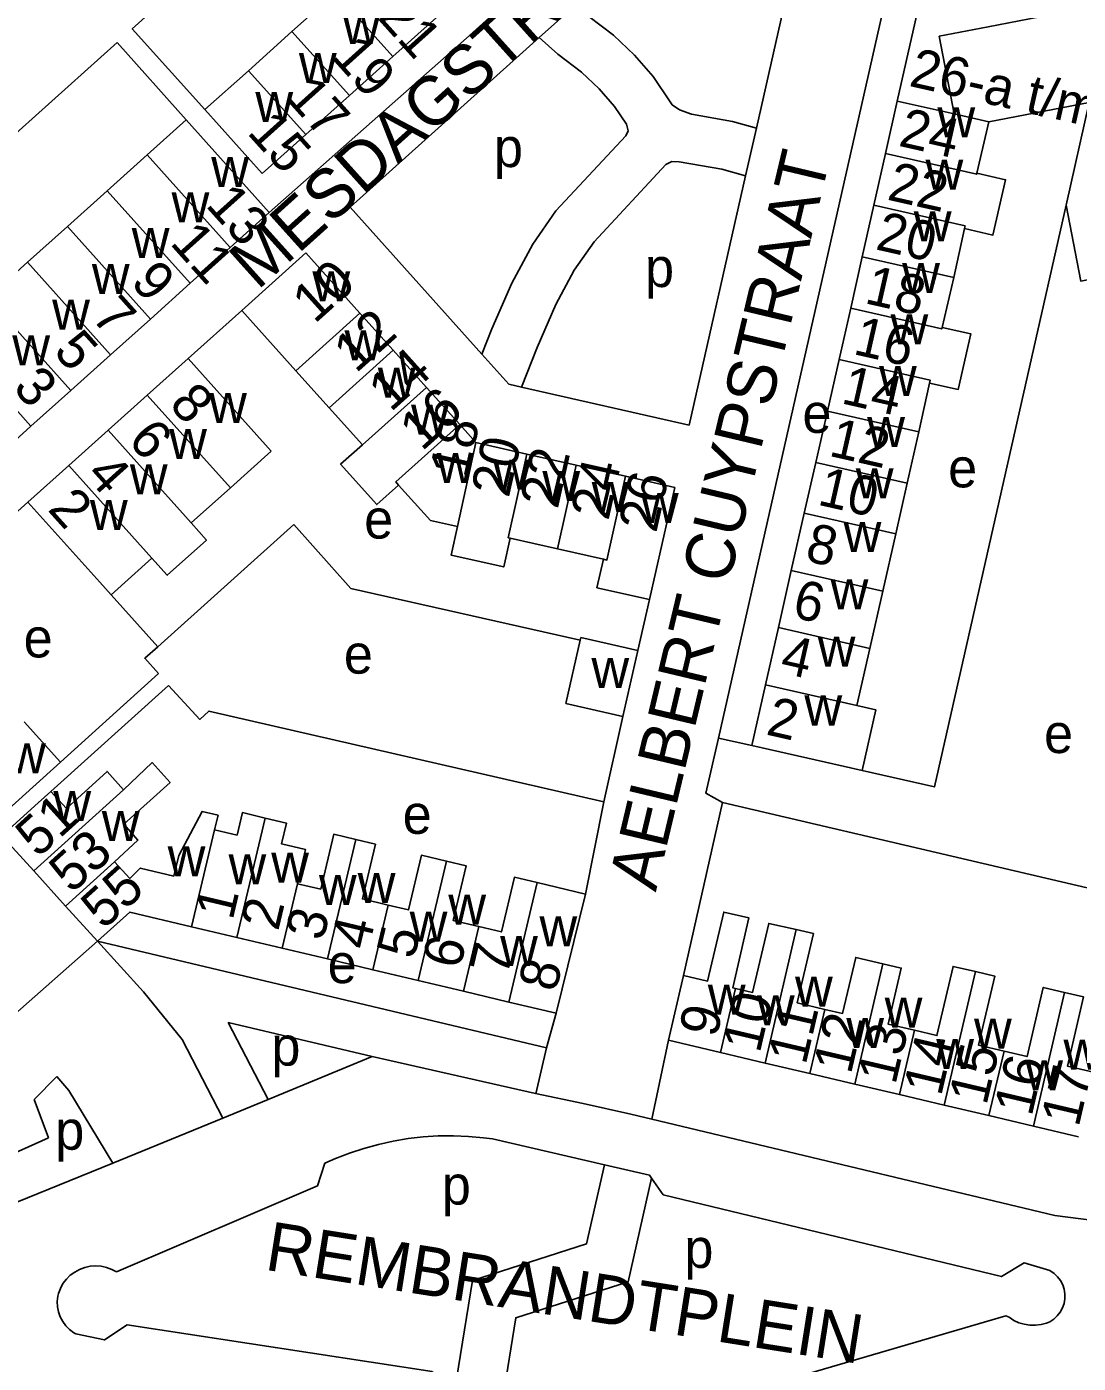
# Model space of a CAD drawing. Extents: x 161775 to 163181, y 382878 to 383925.
# Drawn here: x 162936.2 to 163043.8, y 383281.3 to 383418.1 of the extents above; entities that cross this region are included whole.
import ezdxf

# ---------------------------------------------------------------- set-up
doc = ezdxf.new("R2010")
doc.units = 0
for name, color, linetype in [('BLT_Basislijn', 7, 'Continuous'), ('BLT_Bebouwing', 7, 'Continuous'), ('BLT_Centroide', 7, 'Continuous'), ('BLT_Huisnummer', 7, 'Continuous'), ('BLT_Huisnummer_ tussenligend', 7, 'Continuous'), ('BLT_Huisnummer_reeks', 7, 'Continuous'), ('BLT_Onderverdeling_panden', 7, 'Continuous'), ('BLT_Straatnaam', 7, 'Continuous'), ('BLT_Vlakafsluiter', 7, 'Continuous')]:
    doc.layers.add(name, color=color, linetype=linetype)

msp = doc.modelspace()

# ---------------------------------------------------------------- linework, layer by layer
at = {"layer": 'BLT_Basislijn'}
for p, q in [((162952.51, 383408.57), (162945.42, 383416.49)), ((163034.67, 383408.37), (163044.96, 383410.33)), ((163042.59, 383399.83), (163044.96, 383410.33)), ((162952.69, 383384.12), (162958.19, 383389.05)), ((162949.59, 383354.63), (162963.53, 383367.13)), ((162944.81, 383359.95), (162949.59, 383354.63)), ((162939.61, 383342.8), (162949.66, 383351.88)), ((162950.67, 383350.64), (162938.65, 383339.82)), ((163010.41, 383344.51), (163006.99, 383345.28)), ((162995.25, 383338.75), (162993.38, 383329.29)), ((163007.4, 383338.67), (163003.41, 383320.96)), ((162934.36, 383316.49), (162943.4, 383324.47)), ((162943.4, 383324.47), (162948.14, 383319.29)), ((162943.4, 383324.47), (162989.4, 383313.55)), ((162948.14, 383319.29), (162952.07, 383314.42)), ((162990.37, 383317.12), (162989.4, 383313.55)), ((162960.89, 383308.28), (162956.8, 383316.15)), ((162956.8, 383316.15), (162971.54, 383312.66)), ((162952.07, 383314.42), (162956.25, 383306.37)), ((163001.88, 383314.33), (163000.17, 383306.27)), ((162960.89, 383308.28), (162971.54, 383312.66)), ((162971.54, 383312.66), (162988.26, 383308.87)), ((162989.4, 383313.55), (162988.29, 383308.86)), ((162936.92, 383308.26), (162939.26, 383310.63)), ((162940.47, 383309.19), (162939.26, 383310.63)), ((162940.47, 383309.19), (162944.98, 383301.74)), ((162936.92, 383308.26), (162938.4, 383304.35)), ((162956.25, 383306.37), (162960.89, 383308.28)), ((162944.98, 383301.74), (162956.25, 383306.37)), ((163000.17, 383306.27), (163041.43, 383296.38)), ((162933.27, 383302.06), (162938.4, 383304.35)), ((162983.87, 383304.23), (162995.33, 383301.58)), ((162935.16, 383297.75), (162944.98, 383301.74))]:
    msp.add_line(p, q, dxfattribs=at)
for points in [[(162983.5, 383450.63), (162946.98, 383417.89), (162954.42, 383409.61)], [(162961.01, 383399.09), (163011.63, 383443.87)], [(163014.03, 383439.76), (163016.83, 383434.05), (163010.88, 383407.73)], [(163027.33, 383426.47), (163025.28, 383426.07), (163006.99, 383345.28)], [(162992.39, 383420.35), (162988.64, 383416.99)], [(162992.39, 383420.35), (162993.74, 383419.16), (162996.25, 383417.23), (162998.41, 383415.18), (163000.3, 383412.99), (163002.07, 383410.41), (163002.26, 383410.11), (163003, 383409.58)], [(162988.64, 383416.99), (162969.28, 383399.62), (162982.78, 383384.57)], [(162988.64, 383416.99), (162990.56, 383415.3), (162992.99, 383413.43), (162994.78, 383411.73), (162996.34, 383409.93), (162997.57, 383408.14), (162997.75, 383407.45)], [(162945.42, 383416.49), (162916.97, 383390.95)], [(163010.88, 383407.73), (163008.44, 383408.41), (163004.25, 383409.14), (163003, 383409.58)], [(162982.78, 383384.57), (162983.81, 383387.18), (162985.83, 383391.86), (162987.98, 383395.83), (162990.36, 383399.24), (162997.52, 383406.94), (162997.75, 383407.45)], [(163010.88, 383407.73), (163009.77, 383402.85)], [(162986.83, 383381.2), (162988.43, 383385.27), (162990.33, 383389.67), (162992.24, 383393.19), (162994.26, 383396.09), (163001.61, 383404), (163002.23, 383404.29)], [(163009.77, 383402.85), (163007.34, 383403.53), (163002.96, 383404.28), (163002.23, 383404.29)], [(163009.77, 383402.85), (163003.99, 383377.31)], [(163042.59, 383399.83), (163029.12, 383340.28), (163021.72, 383341.97)], [(163042.59, 383399.83), (163044.1, 383392.05), (163051.6, 383393.51)], [(162982.78, 383384.57), (162985.54, 383381.49), (162986.83, 383381.2)], [(162986.83, 383381.2), (163003.99, 383377.31)], [(162936.29, 383369.41), (162924.89, 383359.2)], [(162963.53, 383367.13), (162969.36, 383360.6), (162992.84, 383355.29)], [(162999.95, 383359.45), (162998.76, 383354.25)], [(162949.66, 383351.88), (162948.25, 383353.45), (162949.59, 383354.63)], [(162950.67, 383350.64), (162953.9, 383347.18), (162954.82, 383348.03), (162995.25, 383338.75)], [(162997.22, 383347.48), (162995.25, 383338.75)], [(163006.99, 383345.28), (163005.71, 383339.63), (163007.4, 383338.67)], [(163057.6, 383326.93), (163007.4, 383338.67)], [(162967.79, 383302.22), (162969.23, 383302.78), (162970.7, 383303.27), (162972.19, 383303.68), (162973.7, 383304.02), (162975.23, 383304.27), (162976.77, 383304.45), (162978.31, 383304.54), (162979.86, 383304.56), (162981.41, 383304.5), (162982.95, 383304.35), (162983.87, 383304.23)], [(162945.37, 383290.62), (162965.93, 383299.43), (162966.7, 383301.75), (162967.79, 383302.22)], [(162995.33, 383301.58), (162993.5, 383293.49), (162981.8, 383289.74), (162979.98, 383278.38)], [(162995.33, 383301.58), (162999.95, 383300.52), (163000.15, 383300.23)], [(163000.15, 383300.23), (162997.74, 383289.6), (162986.25, 383285.92), (162984.93, 383277.67)], [(163000.15, 383300.23), (163001.34, 383298.51), (163035.98, 383290.15), (163038.3, 383291.54), (163040.92, 383290.77)], [(163041.43, 383296.38), (163085.37, 383290.76), (163092.07, 383290.04)], [(162945.37, 383290.62), (162944.87, 383290.88), (162944.34, 383291.08), (162943.79, 383291.2), (162943.22, 383291.24), (162942.66, 383291.2), (162942.11, 383291.08), (162941.58, 383290.88), (162941.08, 383290.61), (162940.63, 383290.27), (162940.23, 383289.88), (162939.88, 383289.43), (162939.61, 383288.93), (162939.41, 383288.41), (162939.34, 383288.14)], [(163040.92, 383285.51), (163041.33, 383285.78), (163041.69, 383286.11), (163041.99, 383286.5), (163042.23, 383286.93), (163042.39, 383287.39), (163042.47, 383287.87), (163042.48, 383288.36), (163042.4, 383288.84), (163042.25, 383289.3), (163042.02, 383289.74), (163041.73, 383290.13), (163041.38, 383290.47), (163040.92, 383290.77)], [(162939.34, 383288.14), (162939.28, 383287.6), (162939.31, 383287.06), (162939.42, 383286.52), (162939.6, 383286.01), (162939.85, 383285.53), (162940.18, 383285.1), (162940.56, 383284.71), (162941, 383284.39), (162941.19, 383284.27)], [(162979.98, 383278.38), (162978.77, 383278.55), (162977.68, 383280.41), (162946.45, 383285.2), (162944.13, 383283.65), (162941.19, 383284.27)], [(163036.75, 383285.98), (163036.44, 383286.13), (163016.34, 383280.25), (163014.95, 383278.24), (163007.37, 383275.92)], [(163036.75, 383285.98), (163037.24, 383285.66), (163037.76, 383285.42), (163038.31, 383285.26), (163038.88, 383285.17), (163039.46, 383285.16), (163040.03, 383285.23), (163040.59, 383285.38), (163040.92, 383285.51)]]:
    msp.add_lwpolyline(points, dxfattribs=at)
at = {"layer": 'BLT_Bebouwing'}
for p, q in [((162973.67, 383415.05), (162978.12, 383419.05)), ((163039.92, 383419.12), (163034.62, 383418.1)), ((162969.21, 383411.05), (162973.67, 383415.05)), ((162964.75, 383407.05), (162969.21, 383411.05)), ((163024.12, 383405.11), (163025.3, 383410.49)), ((163031.13, 383409.17), (163025.3, 383410.49)), ((162960.29, 383403.06), (162954.42, 383409.61)), ((163034.67, 383408.37), (163031.13, 383409.17)), ((163034.67, 383408.37), (163033.47, 383403.12)), ((162960.29, 383403.06), (162964.75, 383407.05)), ((163022.92, 383399.82), (163024.12, 383405.11)), ((163021.73, 383394.55), (163022.92, 383399.82)), ((163032.19, 383397.44), (163031.09, 383392.43)), ((162958.19, 383389.05), (162964.74, 383394.95)), ((163020.54, 383389.29), (163021.73, 383394.55)), ((163031.09, 383392.43), (163029.9, 383387.31)), ((163019.35, 383384.02), (163020.54, 383389.29)), ((162963.73, 383382.88), (162958.19, 383389.05)), ((162948.51, 383380.39), (162952.69, 383384.12)), ((162952.69, 383384.12), (162961.19, 383374.64)), ((163018.15, 383378.75), (163019.35, 383384.02)), ((162967.14, 383379.09), (162963.73, 383382.88)), ((163028.62, 383381.61), (163027.52, 383376.63)), ((162944.49, 383376.79), (162948.51, 383380.39)), ((163016.96, 383373.48), (163018.15, 383378.75)), ((162940.47, 383373.18), (162944.49, 383376.79)), ((163027.52, 383376.63), (163026.33, 383371.36)), ((162957.02, 383370.9), (162961.19, 383374.64)), ((162936.29, 383369.41), (162940.47, 383373.18)), ((163015.79, 383368.29), (163016.96, 383373.48)), ((162953, 383367.3), (162957.02, 383370.9)), ((162999.95, 383359.45), (163002.52, 383370.94)), ((163026.33, 383371.36), (163025.15, 383366.17)), ((162936.29, 383369.41), (162943.64, 383361.25)), ((163014.46, 383362.43), (163015.79, 383368.29)), ((163025.15, 383366.17), (163023.83, 383360.31)), ((162944.81, 383359.95), (162948.98, 383363.69)), ((163013.14, 383356.58), (163014.46, 383362.43)), ((162943.64, 383361.25), (162944.81, 383359.95)), ((163023.83, 383360.31), (163022.5, 383354.46)), ((163011.81, 383350.73), (163013.14, 383356.58)), ((162992.84, 383355.29), (162991.37, 383348.8)), ((162992.9, 383355.57), (162992.84, 383355.29)), ((162992.9, 383355.57), (162998.76, 383354.25)), ((162998.76, 383354.25), (162997.22, 383347.48)), ((163022.5, 383354.46), (163021.18, 383348.61)), ((163010.41, 383344.51), (163011.81, 383350.73)), ((162997.22, 383347.48), (162991.37, 383348.8)), ((162939.61, 383342.8), (162935.91, 383346.92)), ((163019.77, 383342.39), (163010.41, 383344.51)), ((162936.89, 383331.68), (162946.09, 383339.99)), ((162936.89, 383331.68), (162933.63, 383335.28)), ((162940.15, 383328.08), (162945.17, 383332.61)), ((162940.15, 383328.08), (162936.89, 383331.68)), ((162988.42, 383330.47), (162993.38, 383329.29)), ((162993.38, 383329.29), (162990.37, 383317.12)), ((162943.4, 383324.47), (162940.15, 383328.08)), ((162957.69, 383324.86), (162953.05, 383325.96)), ((162962.33, 383323.76), (162957.69, 383324.86)), ((162966.97, 383322.66), (162962.33, 383323.76)), ((162971.6, 383321.55), (162966.97, 383322.66)), ((162976.24, 383320.45), (162971.6, 383321.55)), ((163001.88, 383314.33), (163003.41, 383320.96)), ((162980.88, 383319.35), (162976.24, 383320.45)), ((162985.52, 383318.25), (162980.88, 383319.35)), ((162990.37, 383317.12), (162985.52, 383318.25)), ((163007.2, 383313.08), (163001.88, 383314.33)), ((163011.78, 383312), (163007.2, 383313.08)), ((163016.36, 383310.93), (163011.78, 383312)), ((163020.95, 383309.85), (163016.36, 383310.93)), ((163025.53, 383308.77), (163020.95, 383309.85)), ((163030.11, 383307.69), (163025.53, 383308.77)), ((163034.69, 383306.62), (163030.11, 383307.69)), ((163039.27, 383305.54), (163034.69, 383306.62)), ((163043.86, 383304.46), (163039.27, 383305.54))]:
    msp.add_line(p, q, dxfattribs=at)
for points in [[(163025.3, 383410.49), (163028.06, 383422.69), (163027.33, 383426.47)], [(162963.33, 383417.6), (162967.79, 383421.6)], [(163034.62, 383418.1), (163029.61, 383417.13), (163031.13, 383409.17)], [(162958.87, 383413.6), (162963.33, 383417.6)], [(162954.42, 383409.61), (162958.87, 383413.6)], [(162952.51, 383408.57), (162948.49, 383404.97)], [(162961.01, 383399.09), (162952.51, 383408.57)], [(162948.49, 383404.97), (162944.41, 383401.31)], [(163033.47, 383403.12), (163036.4, 383402.44), (163035.11, 383396.77), (163032.19, 383397.44)], [(162944.41, 383401.31), (162940.33, 383397.65)], [(162956.99, 383395.49), (162961.01, 383399.09)], [(162940.33, 383397.65), (162936.25, 383393.99)], [(162952.92, 383391.83), (162956.99, 383395.49)], [(162964.74, 383394.95), (162970.28, 383388.77)], [(162936.25, 383393.99), (162932.17, 383390.33)], [(162948.84, 383388.17), (162952.92, 383391.83)], [(162944.76, 383384.51), (162948.84, 383388.17)], [(162970.28, 383388.77), (162973.69, 383384.97)], [(163029.9, 383387.31), (163032.83, 383386.66), (163031.55, 383380.96), (163028.62, 383381.61)], [(162940.68, 383380.85), (162944.76, 383384.51)], [(162973.69, 383384.97), (162977.09, 383381.17)], [(162977.09, 383381.17), (162980.5, 383377.38)], [(162936.6, 383377.2), (162940.68, 383380.85)], [(162970.54, 383375.3), (162967.14, 383379.09)], [(162932.55, 383373.56), (162936.6, 383377.2)], [(162980.5, 383377.38), (162982.16, 383375.52)], [(162982.16, 383375.52), (162987.39, 383374.34)], [(162974.25, 383371.17), (162972.01, 383369.17), (162968.31, 383373.3), (162970.54, 383375.3)], [(162987.39, 383374.34), (162992.44, 383373.2)], [(162992.44, 383373.2), (162997.49, 383372.07)], [(162997.49, 383372.07), (163002.52, 383370.94)], [(162980.27, 383366.94), (162977.51, 383367.55), (162974.25, 383371.17)], [(162948.98, 383363.69), (162950.55, 383361.94), (162954.57, 383365.55), (162953, 383367.3)], [(162980.27, 383366.94), (162979.62, 383364.01), (162985.01, 383362.8), (162985.67, 383365.74)], [(162985.67, 383365.74), (162990.52, 383364.64)], [(162990.52, 383364.64), (162995.22, 383363.58)], [(162995.22, 383363.58), (162994.56, 383360.66), (162999.95, 383359.45)], [(163021.18, 383348.61), (163023.11, 383348.18), (163021.72, 383341.97)], [(162932.49, 383336.4), (162939.61, 383342.8)], [(162945.17, 383332.61), (162947.56, 383334.83), (162946.1, 383336.45), (162950.84, 383340.74), (162949.02, 383342.76), (162946.09, 383339.99)], [(162938.65, 383339.82), (162940.23, 383338.08), (162944.4, 383341.86), (162946.09, 383339.99)], [(163021.72, 383341.97), (163019.77, 383342.39)], [(162933.63, 383335.28), (162937.34, 383338.64), (162938.65, 383339.82)], [(162955.41, 383335.89), (162955.76, 383337.37), (162954.13, 383337.76), (162951.74, 383333.26), (162951.24, 383331.15)], [(162960.59, 383337.08), (162958.26, 383337.64), (162957.71, 383335.34), (162955.41, 383335.89)], [(162963.89, 383330.36), (162964.72, 383333.86), (162962.26, 383334.44), (162962.76, 383336.57), (162960.59, 383337.08)], [(162969.87, 383334.88), (162967.6, 383335.42), (162966.27, 383329.81), (162963.89, 383330.36)], [(162973.17, 383328.17), (162970.55, 383328.8), (162971.88, 383334.4), (162969.87, 383334.88)], [(162979.14, 383332.68), (162976.59, 383333.28), (162975.25, 383327.68), (162973.17, 383328.17)], [(162951.24, 383331.15), (162947.8, 383331.96), (162946.71, 383330.91), (162945.17, 383332.61)], [(162982.45, 383325.97), (162979.85, 383326.59), (162981.18, 383332.19), (162979.14, 383332.68)], [(162988.42, 383330.47), (162986.11, 383331.02), (162984.78, 383325.42), (162982.45, 383325.97)], [(162953.05, 383325.96), (162946.71, 383327.46), (162943.4, 383324.47)], [(163003.41, 383320.96), (163005.88, 383320.39), (163007.54, 383327.46), (163010.12, 383326.86), (163008.48, 383319.7), (163008.74, 383319.64)], [(163014.97, 383325.66), (163012.15, 383326.3), (163010.5, 383319.23), (163008.74, 383319.64)], [(163017.9, 383317.5), (163015.06, 383318.16), (163016.72, 383325.26), (163014.97, 383325.66)], [(163023.83, 383322.16), (163021.05, 383322.81), (163019.71, 383317.08), (163017.9, 383317.5)], [(163027.07, 383315.36), (163024.37, 383315.99), (163025.71, 383321.72), (163023.83, 383322.16)], [(163033.31, 383321.36), (163031.02, 383321.9), (163029.37, 383314.82), (163027.07, 383315.36)], [(163036.24, 383313.22), (163033.64, 383313.82), (163035.29, 383320.9), (163033.31, 383321.36)], [(163042.45, 383319.23), (163040.26, 383319.74), (163038.61, 383312.66), (163036.24, 383313.22)], [(163045.4, 383311.07), (163042.74, 383311.7), (163044.39, 383318.77), (163042.45, 383319.23)]]:
    msp.add_lwpolyline(points, dxfattribs=at)
at = {"layer": 'BLT_Onderverdeling_panden'}
for p, q in [((162967.79, 383421.6), (162973.67, 383415.05)), ((162963.33, 383417.6), (162969.21, 383411.05)), ((162958.87, 383413.6), (162964.75, 383407.05)), ((162956.99, 383395.49), (162948.49, 383404.97)), ((162952.92, 383391.83), (162944.41, 383401.31)), ((162948.84, 383388.17), (162940.33, 383397.65)), ((162944.76, 383384.51), (162936.25, 383393.99)), ((163031.09, 383392.43), (163021.73, 383394.55)), ((162940.68, 383380.85), (162932.17, 383390.33)), ((162970.28, 383388.77), (162963.73, 383382.88)), ((162936.6, 383377.2), (162928.1, 383386.68)), ((162973.69, 383384.97), (162967.14, 383379.09)), ((162977.09, 383381.17), (162970.54, 383375.3)), ((162957.02, 383370.9), (162948.51, 383380.39)), ((163027.52, 383376.63), (163018.15, 383378.75)), ((162953, 383367.3), (162944.49, 383376.79)), ((162980.27, 383366.94), (162982.16, 383375.52)), ((162948.98, 383363.69), (162940.47, 383373.18)), ((162990.52, 383364.64), (162992.44, 383373.2)), ((163026.33, 383371.36), (163016.96, 383373.48)), ((163025.15, 383366.17), (163015.79, 383368.29)), ((163023.83, 383360.31), (163014.46, 383362.43)), ((163022.5, 383354.46), (163013.14, 383356.58)), ((163021.18, 383348.61), (163011.81, 383350.73)), ((162955.41, 383335.89), (162953.05, 383325.96)), ((162957.69, 383324.86), (162960.59, 383337.08)), ((162966.97, 383322.66), (162969.87, 383334.88)), ((162976.24, 383320.45), (162979.14, 383332.68)), ((162962.33, 383323.76), (162963.89, 383330.36)), ((162985.52, 383318.25), (162988.42, 383330.47)), ((162971.6, 383321.55), (162973.17, 383328.17)), ((162980.88, 383319.35), (162982.45, 383325.97)), ((163011.78, 383312), (163014.97, 383325.66)), ((163020.95, 383309.85), (163023.83, 383322.16)), ((163007.2, 383313.08), (163008.74, 383319.64)), ((163039.27, 383305.54), (163042.45, 383319.23)), ((163016.36, 383310.93), (163017.9, 383317.5)), ((163025.53, 383308.77), (163027.07, 383315.36)), ((163034.69, 383306.62), (163036.24, 383313.22))]:
    msp.add_line(p, q, dxfattribs=at)
for points in [[(163033.47, 383403.12), (163033.44, 383403), (163024.12, 383405.11)], [(163032.19, 383397.44), (163032.25, 383397.71), (163022.92, 383399.82)], [(163029.9, 383387.31), (163029.87, 383387.17), (163020.54, 383389.29)], [(163028.62, 383381.61), (163028.69, 383381.9), (163019.35, 383384.02)], [(162980.5, 383377.38), (162973.95, 383371.5), (162974.25, 383371.17)], [(162985.67, 383365.74), (162985.47, 383365.78), (162987.39, 383374.34)], [(162995.22, 383363.58), (162995.57, 383363.5), (162997.49, 383372.07)], [(163030.11, 383307.69), (163033.31, 383321.36)]]:
    msp.add_lwpolyline(points, dxfattribs=at)
at = {"layer": 'BLT_Vlakafsluiter'}
for p, q in [((162988.26, 383308.87), (162993.15, 383307.85)), ((162993.15, 383307.85), (162998.04, 383306.78)), ((163000.17, 383306.27), (162998.04, 383306.78))]:
    msp.add_line(p, q, dxfattribs=at)

# ---------------------------------------------------------------- texts
at = {"layer": 'BLT_Centroide'}
for s, p in [('w', (162968.51, 383416.34)), ('w', (162964.04, 383412.34)), ('w', (162959.58, 383408.34)), ('w', (163029.42, 383406.78)), ('p', (162984.01, 383403.73)), ('w', (162955.06, 383401.69)), ('w', (163028.2, 383401.41)), ('w', (162951, 383398.06)), ('w', (163027, 383396.12)), ('w', (162946.92, 383394.41)), ('w', (162942.84, 383390.75)), ('p', (162999.48, 383391.45)), ('w', (163025.81, 383390.84)), ('w', (162965.42, 383389.98)), ('w', (162938.77, 383387.08)), ('w', (163024.62, 383385.59)), ('w', (162934.69, 383383.42)), ('w', (162968.71, 383383.94)), ('w', (162972.12, 383380.12)), ('w', (163023.44, 383380.31)), ('w', (162954.84, 383377.52)), ('e', (163015.6, 383376.52)), ('w', (162975.52, 383376.34)), ('w', (162950.75, 383373.84)), ('w', (163022.23, 383375.06)), ('w', (162978.14, 383371.39)), ('w', (162946.73, 383370.23)), ('w', (162983.92, 383370.69)), ('w', (163021.06, 383369.81)), ('e', (163030.52, 383370.94)), ('w', (162988.97, 383369.55)), ('w', (162994.02, 383368.42)), ('w', (162999.06, 383367.3)), ('w', (162942.64, 383366.56)), ('e', (162970.72, 383365.7)), ('w', (163019.81, 383364.31)), ('w', (163018.48, 383358.44)), ('e', (162935.85, 383353.53)), ('e', (162968.64, 383351.87)), ('w', (163017.16, 383352.59)), ('w', (162993.99, 383350.41)), ('w', (163015.8, 383346.56)), ('e', (163040.34, 383343.74)), ('w', (162934.27, 383341.67)), ('w', (162938.9, 383336.78)), ('e', (162974.66, 383335.47)), ('w', (162943.86, 383334.72)), ('w', (162950.6, 383331.12)), ('w', (162956.83, 383330.31)), ('w', (162961.2, 383330.48)), ('w', (162966.09, 383328.2)), ('w', (162970.06, 383328.38)), ('w', (162979.34, 383326.17)), ('w', (162975.38, 383324.42)), ('w', (162988.67, 383323.95)), ('w', (162984.64, 383321.95)), ('e', (162966.98, 383320.18)), ('w', (163014.84, 383317.78)), ('w', (163005.91, 383316.94)), ('w', (163010.94, 383315.88)), ('w', (163024.02, 383315.64)), ('w', (163020.09, 383313.55)), ('w', (163033.17, 383313.48)), ('p', (162961.22, 383311.74)), ('w', (163029.3, 383311.38)), ('w', (163042.33, 383311.33)), ('w', (163038.42, 383309.22)), ('p', (162939.09, 383303.13)), ('p', (162978.67, 383297.51)), ('p', (163003.51, 383291.03))]:
    msp.add_text(s, height=4, dxfattribs=at).set_placement(p)
at = {"layer": 'BLT_Huisnummer'}
for s, rotation, p in [('19', 311.8861, (162967.27, 383414.98)), ('15', 311.8861, (162958.64, 383407.23)), ('22', 347.2479, (163024.16, 383400.42)), ('13', 311.8934, (162954.39, 383399.79)), ('9', 311.8934, (162946.69, 383391.87)), ('10', 41.8846, (162965.64, 383387.62)), ('18', 347.2479, (163021.85, 383389.82)), ('5', 311.8934, (162938.79, 383384.78)), ('14', 41.8846, (162973.43, 383378.57)), ('14', 347.2479, (163019.45, 383379.57)), ('8', 311.8881, (162950.63, 383379.37)), ('18', 77.3761, (162981.27, 383371.78)), ('22', 77.3761, (162990.53, 383368.63)), ('4', 311.8881, (162942.09, 383372.13)), ('10', 347.2479, (163017.03, 383369.19)), ('26', 77.3761, (163000.62, 383366.19)), ('2', 311.8877, (162938.22, 383368.65)), ('6', 347.2479, (163014.43, 383357.67)), ('2', 347.2479, (163011.76, 383345.66)), ('51', 42.1126, (162937.31, 383332.93)), ('55', 42.1181, (162944.02, 383325.58)), ('1', 76.65, (162957.24, 383326.53)), ('2', 76.6481, (162961.91, 383325.43)), ('4', 76.6485, (162971.15, 383323.48)), ('6', 76.6509, (162980.52, 383321.51)), ('8', 76.64, (162990.35, 383319.18)), ('9', 76.8526, (163006.8, 383314.51)), ('11', 76.8507, (163015.92, 383311.72)), ('13', 76.8487, (163025.11, 383309.69)), ('15', 76.8468, (163034.43, 383307.58)), ('17', 76.847, (163043.87, 383305.35))]:
    msp.add_text(s, height=4, rotation=rotation, dxfattribs=at).set_placement(p)
at = {"layer": 'BLT_Huisnummer_ tussenligend'}
for s, rotation, p in [('21', 311.8861, (162972, 383419)), ('17', 311.8861, (162962.58, 383410.79)), ('24', 347.2479, (163025.33, 383405.93)), ('20', 347.2479, (163022.97, 383395.33)), ('11', 311.8934, (162950.74, 383395.91)), ('7', 311.8934, (162942.68, 383388.29)), ('12', 41.8846, (162969.87, 383382.55)), ('16', 347.2479, (163020.68, 383384.61)), ('3', 311.8934, (162934.64, 383381.06)), ('16', 41.8846, (162976.63, 383374.56)), ('6', 311.8881, (162946.41, 383375.68)), ('12', 347.2479, (163018.19, 383374.19)), ('20', 77.3761, (162985.52, 383369.78)), ('24', 77.3761, (162995.72, 383367.45)), ('8', 347.2479, (163015.75, 383363.45)), ('4', 347.2479, (163013.19, 383352)), ('53', 42.1074, (162940.75, 383329.27)), ('3', 76.6524, (162966.52, 383324.41)), ('5', 76.6446, (162975.82, 383322.53)), ('7', 76.6479, (162985.36, 383320.8)), ('10', 76.8507, (163011.22, 383312.92)), ('12', 76.8487, (163020.55, 383310.76)), ('14', 76.8468, (163029.79, 383308.52)), ('16', 76.8449, (163039.06, 383306.45))]:
    msp.add_text(s, height=4, rotation=rotation, dxfattribs=at).set_placement(p)
at = {"layer": 'BLT_Huisnummer_reeks'}
msp.add_text('26-a t/m c', height=4, rotation=347.2509, dxfattribs=at).set_placement((163026.4, 383412.06))
at = {"layer": 'BLT_Straatnaam'}
for s, height, rotation, p in [('MESDAGSTRAAT', 5, 41.9491, (162959.8, 383391.05)), ('AELBERT CUYPSTRAAT', 5, 76.6295, (163000.58, 383329.46)), ('REMBRANDTPLEIN', 4.9999, 350.9909, (162960.44, 383290.86))]:
    msp.add_text(s, height=height, rotation=rotation, dxfattribs=at).set_placement(p)

doc.saveas('drawing.dxf')
